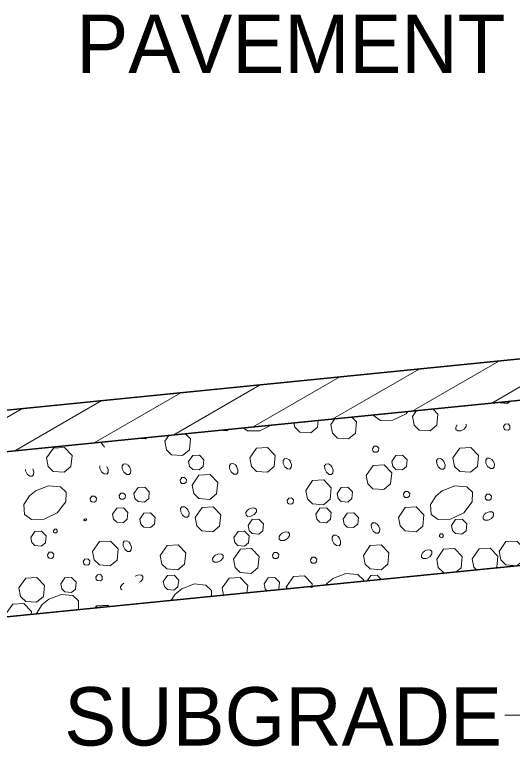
# Model space of a CAD drawing. Extents: x 17672 to 18472, y -9785 to -9267.
# Drawn here: x 17808.45 to 17838.56, y -9339.56 to -9295.31 of the extents above; entities that cross this region are included whole.
import ezdxf

# ---------------------------------------------------------------- set-up
doc = ezdxf.new("R2010")
doc.units = 0
doc.header["$LTSCALE"] = 1.4
for name, color, linetype, lineweight in [('1', 7, 'Continuous', 13), ('15', 7, 'Continuous', 13), ('20', 7, 'Continuous', 25)]:
    doc.layers.add(name, color=color, linetype=linetype, lineweight=lineweight)

msp = doc.modelspace()

# ---------------------------------------------------------------- linework, layer by layer
at = {"layer": '1', "lineweight": 35}
for p, q in [((17945.073, -9305.522), (17802.354, -9319.797)), ((17946.308, -9317.888), (17803.589, -9332.162))]:
    msp.add_line(p, q, dxfattribs=at)
at = {"layer": '1'}
for p, q in [((17837.312, -9318.8), (17842.545, -9315.777)), ((17832.503, -9319.28), (17837.734, -9316.258)), ((17827.692, -9319.76), (17832.925, -9316.741)), ((17822.883, -9320.241), (17828.116, -9317.221)), ((17818.074, -9320.724), (17823.305, -9317.701)), ((17813.263, -9321.204), (17818.496, -9318.182)), ((17808.454, -9321.684), (17813.687, -9318.665)), ((17803.645, -9322.165), (17808.878, -9319.145)), ((17832.508, -9319.616), (17832.761, -9319.253)), ((17827.579, -9320.096), (17827.824, -9319.748)), ((17817.535, -9321.106), (17817.783, -9320.753)), ((17813.658, -9321.165), (17813.891, -9321.456)), ((17821.084, -9330.412), (17820.998, -9329.971))]:
    msp.add_line(p, q, dxfattribs=at)
at = {"layer": '1', "lineweight": 25}
msp.add_line((17824.93, -9330.028), (17824.903, -9329.883), dxfattribs=at)
at = {"layer": '1', "lineweight": 35}
msp.add_lwpolyline([(17802.601, -9322.27), (17873.96, -9315.133), (17874.207, -9317.606), (17945.566, -9310.469)], dxfattribs=at)
at = {"layer": '1', "lineweight": 25}
for points in [[(17838.423, -9318.687), (17838.266, -9318.819), (17837.606, -9318.77), (17837.606, -9318.77)], [(17821.388, -9320.39), (17821.283, -9320.481), (17820.829, -9320.447)], [(17816.445, -9320.885), (17816.354, -9320.961), (17815.971, -9320.934)], [(17813.334, -9331.187), (17813.42, -9331.067), (17814.087, -9331.028), (17814.158, -9331.106)]]:
    msp.add_lwpolyline(points, dxfattribs=at)
at = {"layer": '1'}
for points in [[(17832.234, -9319.307), (17832.128, -9319.442), (17831.329, -9319.841), (17830.575, -9319.853), (17830.15, -9319.552), (17830.148, -9319.515)], [(17833.756, -9319.155), (17834.055, -9319.464), (17833.989, -9320.138), (17833.577, -9320.481), (17832.918, -9320.432), (17832.609, -9320.133), (17832.508, -9319.616)], [(17826.817, -9319.849), (17826.775, -9320.253), (17826.364, -9320.596), (17825.707, -9320.55), (17825.396, -9320.248), (17825.347, -9319.996)], [(17828.839, -9319.648), (17829.126, -9319.944), (17829.06, -9320.618), (17828.648, -9320.961), (17827.989, -9320.912), (17827.68, -9320.613), (17827.579, -9320.096)], [(17823.957, -9320.135), (17823.28, -9320.471), (17822.525, -9320.486), (17822.271, -9320.302)], [(17835.771, -9320.067), (17835.768, -9320.211), (17835.638, -9320.376), (17835.44, -9320.476), (17835.251, -9320.478), (17835.143, -9320.405), (17835.133, -9320.253), (17835.217, -9320.123)], [(17818.79, -9320.65), (17819.082, -9320.954), (17819.016, -9321.628), (17818.604, -9321.971), (17817.945, -9321.925), (17817.636, -9321.623), (17817.535, -9321.106)], [(17825.121, -9322.329), (17825.197, -9322.523), (17825.182, -9322.702), (17825.101, -9322.787), (17824.954, -9322.785), (17824.79, -9322.655), (17824.69, -9322.456), (17824.687, -9322.268), (17824.763, -9322.162), (17824.913, -9322.152), (17825.048, -9322.238), (17825.126, -9322.336)], [(17834.41, -9322.329), (17834.489, -9322.525), (17834.472, -9322.706), (17834.391, -9322.79), (17834.246, -9322.787), (17834.079, -9322.657), (17833.981, -9322.459), (17833.977, -9322.27), (17834.052, -9322.162), (17834.202, -9322.152), (17834.337, -9322.238), (17834.415, -9322.339)], [(17837.393, -9322.304), (17837.469, -9322.501), (17837.454, -9322.679), (17837.374, -9322.765), (17837.227, -9322.763), (17837.062, -9322.633), (17836.962, -9322.432), (17836.959, -9322.243), (17837.035, -9322.138), (17837.185, -9322.128), (17837.32, -9322.214), (17837.398, -9322.312)], [(17814.033, -9322.628), (17814.111, -9322.824), (17814.096, -9323.003), (17814.016, -9323.089), (17813.869, -9323.086), (17813.704, -9322.956), (17813.604, -9322.755), (17813.601, -9322.601)], [(17815.388, -9322.653), (17815.467, -9322.849), (17815.449, -9323.028), (17815.369, -9323.113), (17815.224, -9323.111), (17815.057, -9322.981), (17814.957, -9322.782), (17814.954, -9322.594), (17815.03, -9322.488), (17815.18, -9322.476), (17815.315, -9322.562), (17815.393, -9322.662)], [(17821.878, -9322.63), (17821.957, -9322.827), (17821.94, -9323.005), (17821.859, -9323.091), (17821.714, -9323.089), (17821.547, -9322.959), (17821.447, -9322.758), (17821.445, -9322.569), (17821.521, -9322.464), (17821.67, -9322.454), (17821.805, -9322.54), (17821.883, -9322.638)], [(17827.636, -9322.653), (17827.714, -9322.849), (17827.697, -9323.028), (17827.616, -9323.113), (17827.472, -9323.111), (17827.305, -9322.981), (17827.207, -9322.782), (17827.202, -9322.594), (17827.278, -9322.488), (17827.427, -9322.476), (17827.562, -9322.562), (17827.641, -9322.662)], [(17809.54, -9322.778), (17809.614, -9322.964), (17809.596, -9323.143), (17809.516, -9323.228), (17809.371, -9323.226), (17809.204, -9323.096), (17809.104, -9322.898), (17809.104, -9322.822)], [(17809.717, -9324.108), (17810.498, -9323.8), (17811.217, -9323.861), (17811.557, -9324.184), (17811.545, -9324.768), (17811.028, -9325.429), (17810.229, -9325.829), (17809.474, -9325.844), (17809.05, -9325.54), (17809.011, -9324.942), (17809.354, -9324.403), (17809.748, -9324.089)], [(17834.305, -9324.108), (17835.087, -9323.8), (17835.805, -9323.861), (17836.146, -9324.184), (17836.133, -9324.768), (17835.616, -9325.429), (17834.817, -9325.829), (17834.062, -9325.844), (17833.638, -9325.54), (17833.599, -9324.942), (17833.942, -9324.403), (17834.337, -9324.089)], [(17818.922, -9325.246), (17819.001, -9325.442), (17818.984, -9325.621), (17818.903, -9325.706), (17818.758, -9325.704), (17818.592, -9325.574), (17818.494, -9325.373), (17818.489, -9325.184), (17818.565, -9325.079), (17818.714, -9325.069), (17818.849, -9325.155), (17818.927, -9325.253)], [(17822.611, -9325.214), (17822.807, -9325.135), (17822.986, -9325.15), (17823.072, -9325.231), (17823.07, -9325.378), (17822.94, -9325.542), (17822.741, -9325.643), (17822.552, -9325.648), (17822.445, -9325.572), (17822.435, -9325.42), (17822.521, -9325.287), (17822.621, -9325.209)], [(17836.959, -9325.447), (17837.155, -9325.368), (17837.334, -9325.385), (17837.42, -9325.466), (17837.418, -9325.611), (17837.288, -9325.778), (17837.087, -9325.876), (17836.901, -9325.88), (17836.793, -9325.804), (17836.783, -9325.655), (17836.869, -9325.52), (17836.967, -9325.442)], [(17812.68, -9325.812), (17812.729, -9325.792), (17812.775, -9325.797), (17812.795, -9325.817), (17812.795, -9325.854), (17812.763, -9325.895), (17812.714, -9325.92), (17812.665, -9325.92), (17812.638, -9325.903), (17812.636, -9325.863), (17812.658, -9325.831), (17812.682, -9325.812)], [(17830.459, -9326.214), (17830.538, -9326.41), (17830.521, -9326.589), (17830.44, -9326.675), (17830.295, -9326.672), (17830.128, -9326.542), (17830.03, -9326.341), (17830.025, -9326.153), (17830.101, -9326.047), (17830.251, -9326.037), (17830.386, -9326.123), (17830.464, -9326.224)], [(17824.616, -9326.667), (17824.812, -9326.591), (17824.991, -9326.606), (17825.077, -9326.687), (17825.074, -9326.834), (17824.945, -9326.998), (17824.744, -9327.099), (17824.555, -9327.101), (17824.449, -9327.028), (17824.44, -9326.876), (17824.525, -9326.741), (17824.626, -9326.662)], [(17828.092, -9326.961), (17828.168, -9327.157), (17828.153, -9327.336), (17828.072, -9327.422), (17827.925, -9327.42), (17827.761, -9327.29), (17827.66, -9327.089), (17827.658, -9326.9), (17827.734, -9326.795), (17827.883, -9326.785), (17828.018, -9326.871), (17828.097, -9326.969)], [(17815.44, -9327.307), (17815.518, -9327.503), (17815.501, -9327.682), (17815.42, -9327.768), (17815.275, -9327.765), (17815.111, -9327.635), (17815.008, -9327.434), (17815.006, -9327.246), (17815.082, -9327.14), (17815.231, -9327.13), (17815.366, -9327.216), (17815.444, -9327.314)], [(17820.601, -9327.988), (17820.797, -9327.91), (17820.976, -9327.927), (17821.062, -9328.008), (17821.06, -9328.153), (17820.93, -9328.319), (17820.729, -9328.42), (17820.54, -9328.422), (17820.435, -9328.346), (17820.425, -9328.197), (17820.511, -9328.062), (17820.611, -9327.983)], [(17824.04, -9327.991), (17824.146, -9327.841), (17824.312, -9327.831), (17824.427, -9327.952), (17824.41, -9328.121), (17824.31, -9328.206), (17824.143, -9328.194), (17824.067, -9328.121), (17824.043, -9327.991)], [(17833.229, -9327.758), (17833.425, -9327.682), (17833.604, -9327.697), (17833.69, -9327.778), (17833.687, -9327.922), (17833.557, -9328.089), (17833.359, -9328.189), (17833.17, -9328.192), (17833.062, -9328.116), (17833.052, -9327.966), (17833.138, -9327.831), (17833.239, -9327.753)], [(17833.979, -9328.233), (17834.396, -9327.638), (17835.062, -9327.601), (17835.526, -9328.081), (17835.459, -9328.755), (17835.158, -9329.003)], [(17836.133, -9328.209), (17836.55, -9327.613), (17837.219, -9327.577), (17837.682, -9328.057), (17837.614, -9328.731), (17837.575, -9328.763)], [(17812.599, -9328.38), (17812.702, -9328.233), (17812.871, -9328.224), (17812.986, -9328.344), (17812.969, -9328.513), (17812.866, -9328.599), (17812.702, -9328.586), (17812.623, -9328.51), (17812.599, -9328.383)], [(17834.575, -9329.064), (17834.388, -9329.05), (17834.079, -9328.751), (17833.979, -9328.233)], [(17836.396, -9328.88), (17836.234, -9328.724), (17836.133, -9328.209)], [(17813.361, -9329.331), (17813.467, -9329.182), (17813.633, -9329.172), (17813.748, -9329.292), (17813.734, -9329.461), (17813.631, -9329.547), (17813.464, -9329.535), (17813.388, -9329.461), (17813.364, -9329.331)], [(17815.746, -9329.258), (17815.942, -9329.18), (17816.121, -9329.197), (17816.207, -9329.278), (17816.204, -9329.422), (17816.074, -9329.589), (17816.001, -9329.626)], [(17824.903, -9329.883), (17825.32, -9329.287), (17825.986, -9329.251), (17826.449, -9329.731), (17826.437, -9329.878)], [(17827.704, -9329.407), (17828.486, -9329.099), (17829.204, -9329.16), (17829.545, -9329.483), (17829.545, -9329.567)], [(17829.768, -9329.545), (17829.986, -9329.233), (17830.386, -9329.211), (17830.624, -9329.459)], [(17814.932, -9330.099), (17814.869, -9330.055), (17814.859, -9329.905), (17814.944, -9329.77), (17815.043, -9329.692)], [(17818.523, -9330.05), (17819.305, -9329.738), (17820.023, -9329.8), (17820.364, -9330.126), (17820.359, -9330.486)], [(17820.998, -9329.971), (17821.418, -9329.378), (17822.084, -9329.339), (17822.547, -9329.822), (17822.503, -9330.27)], [(17823.533, -9329.729), (17823.783, -9329.373), (17824.185, -9329.349), (17824.462, -9329.638), (17824.423, -9330.042), (17824.371, -9330.084)], [(17823.709, -9330.15), (17823.594, -9330.037), (17823.533, -9329.729)], [(17827.283, -9329.792), (17827.342, -9329.702), (17827.736, -9329.388)], [(17817.913, -9330.729), (17818.16, -9330.344), (17818.555, -9330.028)], [(17826.623, -9329.859), (17826.426, -9329.954), (17826.21, -9329.9)], [(17810.474, -9330.68), (17811.256, -9330.371), (17811.974, -9330.432), (17812.315, -9330.758), (17812.305, -9331.29)], [(17807.92, -9331.545), (17808.337, -9330.949), (17809.003, -9330.912), (17809.467, -9331.393), (17809.449, -9331.577)], [(17809.77, -9331.545), (17809.768, -9331.513), (17810.111, -9330.976), (17810.506, -9330.66)]]:
    msp.add_lwpolyline(points, dxfattribs=at)
for points in [[(17838.028, -9320.221), (17838.133, -9320.074), (17838.3, -9320.064), (17838.415, -9320.184), (17838.398, -9320.353), (17838.295, -9320.437), (17838.131, -9320.427), (17838.055, -9320.351)], [(17810.376, -9322.118), (17810.792, -9321.523), (17811.459, -9321.486), (17811.925, -9321.966), (17811.856, -9322.64), (17811.444, -9322.981), (17810.785, -9322.934), (17810.476, -9322.633)], [(17822.67, -9322.118), (17823.087, -9321.523), (17823.753, -9321.486), (17824.217, -9321.966), (17824.15, -9322.64), (17823.739, -9322.981), (17823.079, -9322.934), (17822.771, -9322.633)], [(17830.089, -9321.557), (17830.195, -9321.407), (17830.361, -9321.398), (17830.476, -9321.518), (17830.462, -9321.687), (17830.356, -9321.773), (17830.192, -9321.76), (17830.116, -9321.687)], [(17834.964, -9322.118), (17835.381, -9321.523), (17836.048, -9321.486), (17836.513, -9321.966), (17836.445, -9322.64), (17836.033, -9322.981), (17835.374, -9322.934), (17835.065, -9322.633)], [(17818.969, -9322.324), (17819.219, -9321.966), (17819.621, -9321.944), (17819.898, -9322.233), (17819.859, -9322.638), (17819.611, -9322.844), (17819.217, -9322.814), (17819.03, -9322.633)], [(17831.263, -9322.324), (17831.513, -9321.966), (17831.915, -9321.944), (17832.192, -9322.233), (17832.153, -9322.638), (17831.905, -9322.844), (17831.511, -9322.814), (17831.325, -9322.633)], [(17829.712, -9323.17), (17830.128, -9322.577), (17830.795, -9322.537), (17831.261, -9323.018), (17831.192, -9323.692), (17830.78, -9324.035), (17830.121, -9323.986), (17829.812, -9323.687)], [(17819.182, -9323.76), (17819.599, -9323.165), (17820.268, -9323.128), (17820.731, -9323.608), (17820.663, -9324.282), (17820.251, -9324.626), (17819.594, -9324.577), (17819.283, -9324.275)], [(17818.452, -9323.456), (17818.557, -9323.307), (17818.724, -9323.297), (17818.839, -9323.42), (17818.822, -9323.586), (17818.719, -9323.672), (17818.555, -9323.66), (17818.479, -9323.584)], [(17826.06, -9324.079), (17826.476, -9323.486), (17827.143, -9323.447), (17827.606, -9323.927), (17827.54, -9324.601), (17827.128, -9324.944), (17826.472, -9324.895), (17826.16, -9324.596)], [(17815.665, -9324.263), (17815.918, -9323.907), (17816.317, -9323.883), (17816.594, -9324.172), (17816.555, -9324.577), (17816.307, -9324.782), (17815.913, -9324.753), (17815.726, -9324.574)], [(17827.959, -9324.263), (17828.209, -9323.907), (17828.611, -9323.883), (17828.888, -9324.172), (17828.849, -9324.577), (17828.601, -9324.782), (17828.207, -9324.753), (17828.021, -9324.574)], [(17813.008, -9324.577), (17813.114, -9324.427), (17813.28, -9324.42), (17813.395, -9324.54), (17813.381, -9324.706), (17813.275, -9324.792), (17813.111, -9324.78), (17813.035, -9324.706)], [(17814.766, -9324.398), (17814.871, -9324.251), (17815.038, -9324.241), (17815.153, -9324.361), (17815.136, -9324.53), (17815.033, -9324.616), (17814.869, -9324.603), (17814.793, -9324.528)], [(17831.972, -9324.295), (17832.077, -9324.148), (17832.244, -9324.138), (17832.359, -9324.258), (17832.342, -9324.427), (17832.239, -9324.513), (17832.075, -9324.501), (17831.999, -9324.425)], [(17836.913, -9324.461), (17837.016, -9324.312), (17837.185, -9324.304), (17837.3, -9324.425), (17837.283, -9324.591), (17837.18, -9324.677), (17837.016, -9324.665), (17836.937, -9324.591)], [(17824.925, -9324.692), (17825.03, -9324.542), (17825.197, -9324.535), (17825.312, -9324.653), (17825.295, -9324.822), (17825.192, -9324.907), (17825.028, -9324.895), (17824.949, -9324.822)], [(17814.373, -9325.518), (17814.623, -9325.16), (17815.023, -9325.138), (17815.302, -9325.425), (17815.261, -9325.829), (17815.013, -9326.035), (17814.619, -9326.008), (17814.432, -9325.827)], [(17819.369, -9325.714), (17819.785, -9325.121), (17820.452, -9325.081), (17820.915, -9325.564), (17820.849, -9326.236), (17820.437, -9326.579), (17819.778, -9326.532), (17819.469, -9326.231)], [(17826.668, -9325.518), (17826.918, -9325.16), (17827.317, -9325.138), (17827.597, -9325.425), (17827.555, -9325.829), (17827.31, -9326.035), (17826.913, -9326.008), (17826.726, -9325.827)], [(17831.663, -9325.714), (17832.079, -9325.121), (17832.746, -9325.081), (17833.209, -9325.564), (17833.143, -9326.236), (17832.731, -9326.579), (17832.072, -9326.532), (17831.763, -9326.231)], [(17816.018, -9325.812), (17816.268, -9325.454), (17816.67, -9325.432), (17816.947, -9325.719), (17816.908, -9326.123), (17816.66, -9326.329), (17816.266, -9326.3), (17816.079, -9326.121)], [(17828.312, -9325.812), (17828.562, -9325.454), (17828.964, -9325.432), (17829.241, -9325.719), (17829.202, -9326.123), (17828.954, -9326.329), (17828.56, -9326.3), (17828.374, -9326.121)], [(17822.574, -9326.202), (17822.824, -9325.846), (17823.224, -9325.824), (17823.503, -9326.111), (17823.462, -9326.515), (17823.214, -9326.721), (17822.82, -9326.692), (17822.633, -9326.513)], [(17834.869, -9326.202), (17835.119, -9325.846), (17835.518, -9325.824), (17835.798, -9326.111), (17835.756, -9326.515), (17835.508, -9326.721), (17835.114, -9326.692), (17834.927, -9326.513)], [(17809.417, -9326.927), (17809.667, -9326.569), (17810.069, -9326.547), (17810.346, -9326.836), (17810.305, -9327.241), (17810.06, -9327.447), (17809.663, -9327.417), (17809.479, -9327.238)], [(17810.79, -9326.52), (17810.851, -9326.429), (17810.952, -9326.425), (17811.02, -9326.498), (17811.011, -9326.599), (17810.949, -9326.65), (17810.851, -9326.643), (17810.805, -9326.596)], [(17821.712, -9326.927), (17821.962, -9326.569), (17822.361, -9326.547), (17822.641, -9326.836), (17822.601, -9327.241), (17822.354, -9327.447), (17821.959, -9327.417), (17821.773, -9327.238)], [(17834.146, -9326.795), (17834.207, -9326.704), (17834.307, -9326.699), (17834.378, -9326.77), (17834.369, -9326.871), (17834.305, -9326.922), (17834.207, -9326.915), (17834.16, -9326.871)], [(17813.165, -9327.773), (17813.582, -9327.177), (17814.248, -9327.14), (17814.714, -9327.621), (17814.645, -9328.295), (17814.234, -9328.638), (17813.574, -9328.589), (17813.266, -9328.287)], [(17817.251, -9328.013), (17817.668, -9327.417), (17818.337, -9327.38), (17818.8, -9327.861), (17818.731, -9328.535), (17818.32, -9328.878), (17817.663, -9328.829), (17817.351, -9328.53)], [(17829.545, -9328.013), (17829.964, -9327.417), (17830.631, -9327.38), (17831.094, -9327.861), (17831.026, -9328.535), (17830.614, -9328.878), (17829.957, -9328.829), (17829.646, -9328.53)], [(17837.753, -9327.773), (17838.17, -9327.177), (17838.837, -9327.14), (17839.303, -9327.621), (17839.234, -9328.295), (17838.822, -9328.638), (17838.163, -9328.589), (17837.854, -9328.287)], [(17810.425, -9327.974), (17810.528, -9327.824), (17810.694, -9327.814), (17810.812, -9327.934), (17810.795, -9328.104), (17810.692, -9328.189), (17810.528, -9328.177), (17810.449, -9328.101)], [(17821.685, -9328.233), (17822.101, -9327.638), (17822.768, -9327.601), (17823.231, -9328.081), (17823.165, -9328.755), (17822.753, -9329.099), (17822.094, -9329.05), (17821.785, -9328.751)], [(17826.344, -9328.273), (17826.447, -9328.126), (17826.614, -9328.116), (17826.729, -9328.236), (17826.714, -9328.405), (17826.611, -9328.488), (17826.445, -9328.479), (17826.369, -9328.403)], [(17817.442, -9329.591), (17817.692, -9329.233), (17818.092, -9329.211), (17818.371, -9329.501), (17818.329, -9329.905), (17818.084, -9330.111), (17817.687, -9330.081), (17817.503, -9329.9)], [(17808.704, -9329.971), (17809.123, -9329.378), (17809.79, -9329.339), (17810.253, -9329.822), (17810.185, -9330.493), (17809.773, -9330.836), (17809.116, -9330.79), (17808.805, -9330.488)], [(17811.239, -9329.729), (17811.489, -9329.373), (17811.891, -9329.349), (17812.168, -9329.638), (17812.128, -9330.042), (17811.881, -9330.246), (17811.486, -9330.219), (17811.3, -9330.037)]]:
    msp.add_lwpolyline(points, close=True, dxfattribs=at)
at = {"layer": '15'}
msp.add_line((17838.106, -9337.675), (17845.045, -9337.675), dxfattribs=at)

# ---------------------------------------------------------------- texts
at = {"layer": '20'}
for s, p in [('PAVEMENT', (17812.175, -9298.843)), ('SUBGRADE', (17811.447, -9339.506))]:
    msp.add_text(s, height=3.529, dxfattribs=at).set_placement(p)

doc.saveas('drawing.dxf')
